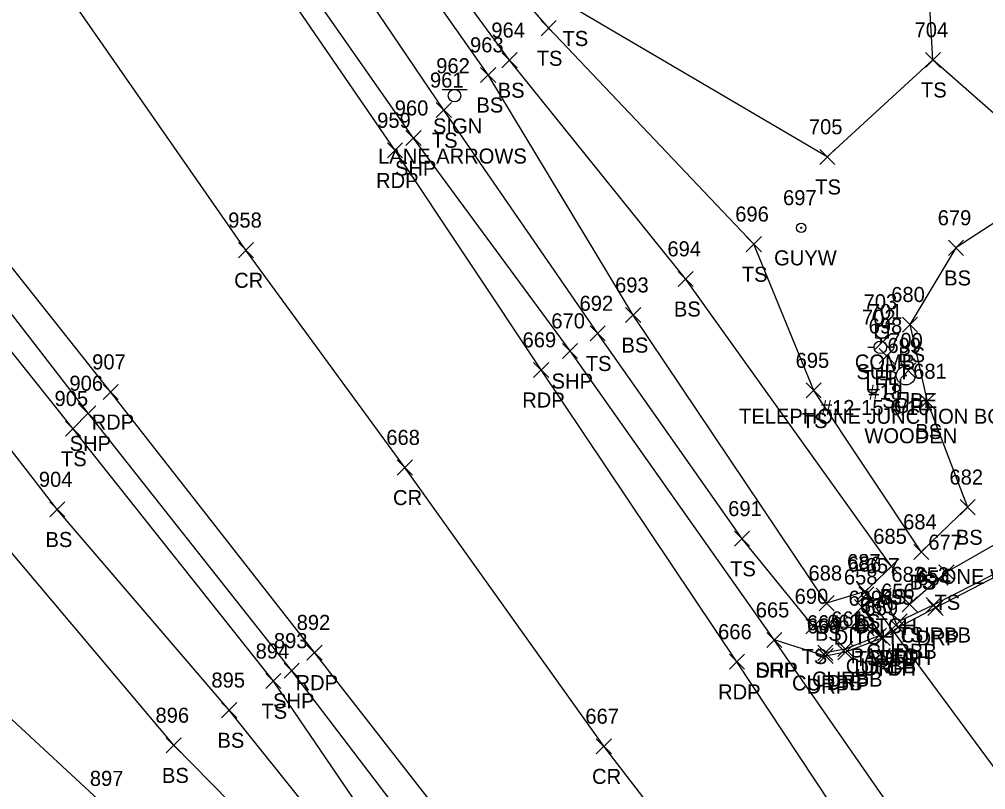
# Model space of a CAD drawing. Extents: x 1623612 to 1625808, y 621345 to 627748.
# Drawn here: x 1624906.2 to 1625034.6, y 626000.5 to 626102.9 of the extents above; entities that cross this region are included whole.
import ezdxf

# ---------------------------------------------------------------- set-up
doc = ezdxf.new("R2010")
doc.units = 0
for name, color, linetype in [('D_A', 7, 'Continuous'), ('D_C', 7, 'Continuous'), ('D_I', 7, 'Continuous'), ('D_TIC', 7, 'Continuous'), ('DCP', 7, 'Continuous'), ('DD', 7, 'Continuous'), ('L_A', 7, 'Continuous'), ('L_I', 7, 'Continuous'), ('L_TIC', 7, 'Continuous'), ('LELB', 7, 'Continuous'), ('LSOGP', 7, 'Continuous'), ('P_A', 7, 'Continuous'), ('P_I', 7, 'Continuous'), ('P_TIC', 7, 'Continuous'), ('PET', 7, 'Continuous'), ('PRC', 7, 'Continuous'), ('PSP', 7, 'Continuous'), ('R_A', 7, 'Continuous'), ('R_C', 7, 'Continuous'), ('R_I', 7, 'Continuous'), ('R_TIC', 7, 'Continuous'), ('RC', 7, 'Continuous'), ('RDP', 7, 'Continuous'), ('RGP', 7, 'Continuous'), ('S_A', 7, 'Continuous'), ('S_C', 7, 'Continuous'), ('S_I', 7, 'Continuous'), ('SSGN', 7, 'Continuous'), ('U_A', 7, 'Continuous'), ('U_C', 7, 'Continuous'), ('U_I', 7, 'Continuous'), ('U_TIC', 7, 'Continuous'), ('UDEFAULT', 7, 'Continuous'), ('UP', 7, 'Continuous'), ('UPGW', 7, 'Continuous')]:
    doc.layers.add(name, color=color, linetype=linetype)

msp = doc.modelspace()

# ---------------------------------------------------------------- linework, layer by layer
at = {"layer": 'D_TIC'}
for points in [[(1625017.74, 626025.52), (1625019.74, 626027.52)], [(1625019.74, 626025.52), (1625017.74, 626027.52)], [(1625020.06, 626025.33), (1625022.06, 626027.33)], [(1625022.06, 626025.33), (1625020.06, 626027.33)], [(1625017.17, 626023.82), (1625019.17, 626025.82)], [(1625019.17, 626023.82), (1625017.17, 626025.82)], [(1625021.95, 626021.12), (1625023.95, 626023.12)], [(1625023.95, 626021.12), (1625021.95, 626023.12)], [(1625019.92, 626019.71), (1625021.92, 626021.71)], [(1625021.92, 626019.71), (1625019.92, 626021.71)]]:
    msp.add_lwpolyline(points, dxfattribs=at)
at = {"layer": 'DCP'}
msp.add_lwpolyline([(1625053.65, 625979.21), (1625018.74, 626026.52)], dxfattribs=at)
at = {"layer": 'DD'}
msp.add_lwpolyline([(1625022.95, 626022.12), (1625021.06, 626026.33), (1625018.17, 626024.82), (1625020.92, 626020.71)], dxfattribs=at)
at = {"layer": 'L_TIC'}
for points in [[(1624975.55, 626100.74), (1624977.55, 626102.74)], [(1624977.55, 626100.74), (1624975.55, 626102.74)], [(1624970.34, 626096.49), (1624972.34, 626098.49)], [(1624972.34, 626096.49), (1624970.34, 626098.49)], [(1625026.59, 626096.53), (1625028.59, 626098.53)], [(1625028.59, 626096.53), (1625026.59, 626098.53)], [(1624967.51, 626094.53), (1624969.51, 626096.53)], [(1624969.51, 626094.53), (1624967.51, 626096.53)], [(1624961.62, 626089.85), (1624963.62, 626091.85)], [(1624963.62, 626089.85), (1624961.62, 626091.85)], [(1625012.55, 626083.64), (1625014.55, 626085.64)], [(1625014.55, 626083.64), (1625012.55, 626085.64)], [(1625002.8, 626072.04), (1625004.8, 626074.04)], [(1625004.8, 626072.04), (1625002.8, 626074.04)], [(1625029.64, 626071.55), (1625031.64, 626073.55)], [(1625031.64, 626071.55), (1625029.64, 626073.55)], [(1624993.73, 626067.42), (1624995.73, 626069.42)], [(1624995.73, 626067.42), (1624993.73, 626069.42)], [(1624986.77, 626062.62), (1624988.77, 626064.62)], [(1624988.77, 626062.62), (1624986.77, 626064.62)], [(1625023.54, 626061.35), (1625025.54, 626063.35)], [(1625025.54, 626061.35), (1625023.54, 626063.35)], [(1624982.06, 626060.18), (1624984.06, 626062.18)], [(1624984.06, 626060.18), (1624982.06, 626062.18)], [(1625010.76, 626052.6), (1625012.76, 626054.6)], [(1625012.76, 626052.6), (1625010.76, 626054.6)], [(1625025.8, 626051.15), (1625027.8, 626053.15)], [(1625027.8, 626051.15), (1625025.8, 626053.15)], [(1624912.35, 626047.53), (1624914.35, 626049.53)], [(1624914.35, 626047.53), (1624912.35, 626049.53)], [(1624910.27, 626036.79), (1624912.27, 626038.79)], [(1624912.27, 626036.79), (1624910.27, 626038.79)], [(1625031.19, 626037.09), (1625033.19, 626039.09)], [(1625033.19, 626037.09), (1625031.19, 626039.09)], [(1625001.24, 626032.9), (1625003.24, 626034.9)], [(1625003.24, 626032.9), (1625001.24, 626034.9)], [(1625025.04, 626031.14), (1625027.04, 626033.14)], [(1625027.04, 626031.14), (1625025.04, 626033.14)], [(1625025.04, 626031.14), (1625027.04, 626033.14)], [(1625027.04, 626031.14), (1625025.04, 626033.14)], [(1625021.07, 626029.22), (1625023.07, 626031.22)], [(1625023.07, 626029.22), (1625021.07, 626031.22)], [(1625021.07, 626029.22), (1625023.07, 626031.22)], [(1625023.07, 626029.22), (1625021.07, 626031.22)], [(1625028.39, 626028.44), (1625030.39, 626030.44)], [(1625030.39, 626028.44), (1625028.39, 626030.44)], [(1625017.59, 626025.86), (1625019.59, 626027.86)], [(1625019.59, 626025.86), (1625017.59, 626027.86)], [(1625012.47, 626024.33), (1625014.47, 626026.33)], [(1625014.47, 626024.33), (1625012.47, 626026.33)], [(1625023.48, 626024.16), (1625025.48, 626026.16)], [(1625025.48, 626024.16), (1625023.48, 626026.16)], [(1625010.72, 626021.24), (1625012.72, 626023.24)], [(1625012.72, 626021.24), (1625010.72, 626023.24)], [(1625017.79, 626020.99), (1625019.79, 626022.99)], [(1625019.79, 626020.99), (1625017.79, 626022.99)], [(1624938.98, 626013.97), (1624940.98, 626015.97)], [(1624940.98, 626013.97), (1624938.98, 626015.97)], [(1624933.11, 626010.11), (1624935.11, 626012.11)], [(1624935.11, 626010.11), (1624933.11, 626012.11)], [(1624925.74, 626005.44), (1624927.74, 626007.44)], [(1624927.74, 626005.44), (1624925.74, 626007.44)]]:
    msp.add_lwpolyline(points, dxfattribs=at)
at = {"layer": 'LELB'}
for points in [[(1624922.62, 625919.78), (1624947.1, 625948.56), (1624957.29, 625967.96), (1624961.07, 625979.24), (1624958.14, 625988.32), (1624939.98, 626014.97), (1624913.35, 626048.53), (1624887.64, 626080.72), (1624849.69, 626124.89), (1624827.87, 626147.28), (1624809.41, 626168.54), (1624784.36, 626180.38), (1624768.54, 626181.82), (1624752.66, 626178.59), (1624735.62, 626165.38), (1624717.35, 626142.72), (1624703.97, 626118.88), (1624686.38, 626080.62)], [(1624955.96, 625983.78), (1624934.11, 626011.11), (1624911.27, 626037.79), (1624882.4, 626075.05), (1624844.35, 626119.9), (1624824.36, 626144.8), (1624806.17, 626164.83), (1624787.45, 626176.55), (1624783.93, 626178.73), (1624767.98, 626179.73), (1624754.07, 626176), (1624742, 626162.74), (1624739.77, 626159.16), (1624724.1, 626139.19), (1624712.05, 626114.81), (1624693.63, 626076.88), (1624682.43, 626045.31), (1624675.97, 626009.13), (1624661.01, 625972.63), (1624643.83, 625915.97), (1624628.3, 625870.19), (1624627.01, 625849.3)], [(1624955.96, 625983.78), (1624951.7, 625981.09), (1624926.74, 626006.44), (1624903, 626034.62), (1624876.22, 626070.88), (1624844.75, 626108.46), (1624819.16, 626140.11), (1624799.87, 626157.38), (1624783.22, 626162.54), (1624755.55, 626163.6), (1624745.94, 626159.17), (1624742.5, 626157.44), (1624728.24, 626136.03), (1624714.3, 626113.6), (1624699.16, 626074.97), (1624693.78, 626039.85), (1624688.78, 626004.07), (1624672.44, 625966.06), (1624654.5, 625913.12), (1624647.49, 625863.39), (1624632.05, 625839.96), (1624633.8, 625804.37), (1624607.9, 625781.97), (1624576.85, 625750.09)], [(1625027.59, 626097.53), (1625013.55, 626084.64), (1624979.97, 626104.37), (1624954.09, 626138.14), (1624945.55, 626148.22)], [(1624950.51, 625967.41), (1624917.97, 625998.05), (1624890.03, 626023.9), (1624863.39, 626055.21), (1624827.77, 626091.06), (1624802.93, 626124.92), (1624791, 626136.13), (1624749.2, 626141.33), (1624736.73, 626113.9), (1624711.77, 626069.81), (1624693.78, 626039.85)], [(1625026.04, 626032.14), (1625011.76, 626053.6), (1625003.8, 626073.04), (1624976.55, 626101.74), (1624945.6, 626137.25), (1624941.49, 626135.55), (1624937.63, 626127.8)], [(1625022.07, 626030.22), (1625018.59, 626026.86), (1625013.47, 626025.33), (1624987.77, 626063.62), (1624968.51, 626095.53), (1624943.29, 626131.48), (1624945.22, 626133.16)], [(1625022.07, 626030.22), (1624994.73, 626068.42), (1624971.34, 626097.49), (1624945.22, 626133.16)], [(1625018.79, 626021.99), (1625011.72, 626022.24), (1625002.24, 626033.9), (1624983.06, 626061.18), (1624962.62, 626090.85), (1624937.63, 626127.8)], [(1625045.18, 626082.05), (1625030.64, 626072.55), (1625024.54, 626062.35), (1625026.8, 626052.15), (1625032.19, 626038.09), (1625026.04, 626032.14)], [(1625058.49, 626067.08), (1625039.14, 626056.58), (1625038.67, 626047.76), (1625042.58, 626036.99), (1625029.39, 626029.44), (1625024.48, 626025.16)]]:
    msp.add_lwpolyline(points, dxfattribs=at)
at = {"layer": 'LSOGP'}
msp.add_lwpolyline([(1625200.23, 625842.69), (1625180.7, 625879.29), (1625153.81, 625905.72), (1625139.96, 625942.2), (1625106.19, 625988.13), (1625099.02, 625990.77), (1625092.97, 625994.26), (1625089.75, 626000.84), (1625088.99, 626008.69), (1625090.67, 626015.53), (1625069.92, 626043.19), (1625069.59, 626043.56), (1625065.69, 626051.8), (1625058.49, 626067.08), (1625045.18, 626082.05), (1625027.59, 626097.53), (1625025.64, 626131.89)], dxfattribs=at)
at = {"layer": 'P_TIC'}
for points in [[(1624957.59, 626086.14), (1624959.59, 626088.14)], [(1624959.59, 626086.14), (1624957.59, 626088.14)], [(1624955.14, 626084.5), (1624957.14, 626086.5)], [(1624957.14, 626084.5), (1624955.14, 626086.5)], [(1624935.34, 626071.24), (1624937.34, 626073.24)], [(1624937.34, 626071.24), (1624935.34, 626073.24)], [(1624978.39, 626057.85), (1624980.39, 626059.85)], [(1624980.39, 626057.85), (1624978.39, 626059.85)], [(1624974.55, 626055.33), (1624976.55, 626057.33)], [(1624976.55, 626055.33), (1624974.55, 626057.33)], [(1624917.36, 626052.4), (1624919.36, 626054.4)], [(1624919.36, 626052.4), (1624917.36, 626054.4)], [(1624914.38, 626049.56), (1624916.38, 626051.56)], [(1624916.38, 626049.56), (1624914.38, 626051.56)], [(1624956.44, 626042.36), (1624958.44, 626044.36)], [(1624958.44, 626042.36), (1624956.44, 626044.36)], [(1625005.51, 626019.44), (1625007.51, 626021.44)], [(1625007.51, 626019.44), (1625005.51, 626021.44)], [(1624944.44, 626017.77), (1624946.44, 626019.77)], [(1624946.44, 626017.77), (1624944.44, 626019.77)], [(1625000.56, 626016.54), (1625002.56, 626018.54)], [(1625002.56, 626016.54), (1625000.56, 626018.54)], [(1624941.41, 626015.35), (1624943.41, 626017.35)], [(1624943.41, 626015.35), (1624941.41, 626017.35)], [(1624982.87, 626005.31), (1624984.87, 626007.31)], [(1624984.87, 626005.31), (1624982.87, 626007.31)]]:
    msp.add_lwpolyline(points, dxfattribs=at)
at = {"layer": 'PET'}
for points in [[(1625223.77, 625705.98), (1625197.34, 625741.92), (1625177.42, 625768.95), (1625149.4, 625806.39), (1625126.15, 625837.91), (1625100.61, 625872.87), (1625078.39, 625904.23), (1625050.83, 625943.53), (1625026.61, 625979.68), (1625001.56, 626017.54), (1624975.55, 626056.33), (1624956.14, 626085.5), (1624926, 626129.47), (1624907.51, 626155.92), (1624881.56, 626192.36), (1624859.36, 626223.09), (1624835.81, 626254.93), (1624815.05, 626283.37), (1624795.69, 626312.41), (1624789.97, 626324.03), (1624786.26, 626337.17), (1624785.07, 626353.04), (1624787.66, 626371.25), (1624792.4, 626386.87)], [(1625203.84, 625692.06), (1625178.56, 625725.93), (1625159.1, 625752.13), (1625138.75, 625779.51), (1625115.85, 625810.21), (1625086.53, 625849.64), (1625062.28, 625882.29), (1625040.04, 625911.41), (1625011.87, 625940.67), (1624992.38, 625961.15), (1624963.94, 625995.04), (1624945.44, 626018.77), (1624918.36, 626053.4), (1624893.3, 626084.98), (1624858.44, 626129.32)]]:
    msp.add_lwpolyline(points, dxfattribs=at)
at = {"layer": 'PRC'}
msp.add_lwpolyline([(1625213.58, 625698.73), (1625187.25, 625734.61), (1625167.02, 625761.6), (1625139.37, 625799.19), (1625115.73, 625830.47), (1625089.34, 625866.2), (1625066.75, 625896.39), (1625037.44, 625935.12), (1625012.58, 625969.02), (1624983.87, 626006.31), (1624957.44, 626043.36), (1624936.34, 626072.24), (1624905.82, 626116.16), (1624884.45, 626141.57), (1624859.03, 626175.57)], dxfattribs=at)
at = {"layer": 'PSP'}
for points in [[(1625197.89, 625687.83), (1625193.57, 625693.81), (1625173.65, 625722.07), (1625153.52, 625749.21), (1625132.81, 625774.23), (1625108.64, 625805.39), (1625079.11, 625843.61), (1625053.93, 625876.29), (1625030.83, 625905.94), (1625006.8, 625934.64), (1624989.43, 625958.35), (1624960.91, 625992.11), (1624942.41, 626016.35), (1624915.38, 626050.56), (1624890.43, 626082.85), (1624855.5, 626126.62)], [(1625229.23, 625710.23), (1625203.41, 625745.51), (1625190.36, 625762.87), (1625182.48, 625773.25), (1625155.83, 625810.32), (1625133.5, 625842.77), (1625108.2, 625877.47), (1625085.19, 625909.84), (1625057.82, 625948.13), (1625042.32, 625969.75), (1625027.64, 625990.04), (1625006.51, 626020.44), (1624979.39, 626058.85), (1624958.59, 626087.14), (1624930.55, 626127.2)]]:
    msp.add_lwpolyline(points, dxfattribs=at)
at = {"layer": 'R_TIC'}
for points in [[(1625026.69, 626024.1), (1625028.69, 626026.1)], [(1625028.69, 626024.1), (1625026.69, 626026.1)], [(1625026.93, 626023.71), (1625028.93, 626025.71)], [(1625028.93, 626023.71), (1625026.93, 626025.71)], [(1625022.16, 626021.93), (1625024.16, 626023.93)], [(1625024.16, 626021.93), (1625022.16, 626023.93)], [(1625021.95, 626021.12), (1625023.95, 626023.12)], [(1625023.95, 626021.12), (1625021.95, 626023.12)], [(1625005.51, 626019.44), (1625007.51, 626021.44)], [(1625007.51, 626019.44), (1625005.51, 626021.44)], [(1625019.42, 626020), (1625021.42, 626022)], [(1625021.42, 626020), (1625019.42, 626022)], [(1625019.92, 626019.71), (1625021.92, 626021.71)], [(1625021.92, 626019.71), (1625019.92, 626021.71)], [(1625014.95, 626018.24), (1625016.95, 626020.24)], [(1625016.95, 626018.24), (1625014.95, 626020.24)], [(1625012.29, 626017.73), (1625014.29, 626019.73)], [(1625014.29, 626017.73), (1625012.29, 626019.73)], [(1625012.33, 626017.3), (1625014.33, 626019.3)], [(1625014.33, 626017.3), (1625012.33, 626019.3)], [(1625014.97, 626017.8), (1625016.97, 626019.8)], [(1625016.97, 626017.8), (1625014.97, 626019.8)]]:
    msp.add_lwpolyline(points, dxfattribs=at)
at = {"layer": 'RC'}
for points in [[(1625069.59, 626043.56), (1625057.37, 626039.13), (1625043.4, 626033.1), (1625027.69, 626025.1), (1625023.16, 626022.93)], [(1625020.42, 626021), (1625015.95, 626019.24), (1625013.29, 626018.73)]]:
    msp.add_lwpolyline(points, dxfattribs=at)
at = {"layer": 'RDP'}
msp.add_lwpolyline([(1625069.92, 626043.19), (1625057.28, 626038.97), (1625043.66, 626032.88), (1625027.93, 626024.71), (1625022.95, 626022.12), (1625020.92, 626020.71), (1625015.97, 626018.8), (1625013.33, 626018.3), (1625006.51, 626020.44)], dxfattribs=at)
at = {"layer": 'RGP'}
msp.add_line((1625023.97, 626055.58), (1625023.97, 626055.58), dxfattribs=at)
for radius in [1.25, 0.0833]:
    msp.add_circle((1625023.97, 626055.58), radius, dxfattribs=at)
at = {"layer": 'SSGN'}
for p, q in [((1624962.39, 626093.6), (1624965.73, 626093.6)), ((1624964.04, 626092.77), (1624964.04, 626092.77))]:
    msp.add_line(p, q, dxfattribs=at)
msp.add_circle((1624964.04, 626092.77), 0.833, dxfattribs=at)
at = {"layer": 'U_TIC'}
for points in [[(1625019.93, 626059.09), (1625021.93, 626061.09)], [(1625021.93, 626059.09), (1625019.93, 626061.09)], [(1625023.31, 626055.25), (1625025.31, 626057.25)], [(1625025.31, 626055.25), (1625023.31, 626057.25)]]:
    msp.add_lwpolyline(points, dxfattribs=at)
at = {"layer": 'UDEFAULT'}
for points in [[(1625020.46, 626057.17), (1625022.46, 626059.17)], [(1625022.46, 626057.17), (1625020.46, 626059.17)]]:
    msp.add_lwpolyline(points, dxfattribs=at)
at = {"layer": 'UP'}
for p, q in [((1625021.07, 626063.05), (1625020.82, 626062.21)), ((1625019.99, 626060.55), (1625019.99, 626062.21)), ((1625019.99, 626062.21), (1625021.65, 626062.21)), ((1625020.82, 626061.38), (1625020.82, 626061.38)), ((1625021.65, 626062.21), (1625021.65, 626060.55)), ((1625021.65, 626060.55), (1625019.99, 626060.55)), ((1625020.57, 626059.71), (1625020.82, 626060.55)), ((1625018.94, 626059.33), (1625019.76, 626059.33)), ((1625020.6, 626059.33), (1625020.6, 626059.33)), ((1625022.26, 626059.33), (1625021.43, 626059.33)), ((1625021.43, 626059.33), (1625021.43, 626059.33)), ((1625022.26, 626059.33), (1625022.26, 626059.33))]:
    msp.add_line(p, q, dxfattribs=at)
for centre in [(1625020.82, 626061.38), (1625020.6, 626059.33)]:
    msp.add_circle(centre, 0.833, dxfattribs=at)
at = {"layer": 'UPGW'}
for radius in [0.625, 0.0833]:
    msp.add_circle((1625010.09, 626075.22), radius, dxfattribs=at)

# ---------------------------------------------------------------- texts
at = {"layer": 'D_A'}
for s, p in [('DITCH', (1625017.29, 626021.33)), ('P', (1625018.12, 626021.52)), ('DITCH', (1625014.4, 626019.82)), ('DITCH', (1625019.19, 626017.12)), ('DITCH', (1625017.16, 626015.71))]:
    msp.add_text(s, height=2, dxfattribs=at).set_placement(p)
at = {"layer": 'D_C'}
msp.add_text('PAVED', height=2, dxfattribs=at).set_placement((1625016.64, 626017.33))
at = {"layer": 'D_I'}
for s, p in [('686', (1625016.28, 626029.52)), ('657', (1625018.65, 626029.33)), ('658', (1625015.76, 626027.82)), ('655', (1625020.54, 626025.12)), ('659', (1625018.5, 626023.71))]:
    msp.add_text(s, height=2, dxfattribs=at).set_placement(p)
at = {"layer": 'L_A'}
for s, p in [('TS', (1624978.38, 626099.37)), ('TS', (1624974.96, 626096.74)), ('BS', (1624969.78, 626092.49)), ('TS', (1625026, 626092.53)), ('BS', (1624966.95, 626090.53)), ('TS', (1624961.03, 626085.85)), ('TS', (1625011.96, 626079.64)), ('TS', (1625002.2, 626068.04)), ('BS', (1625029.08, 626067.55)), ('BS', (1624993.18, 626063.42)), ('BS', (1624986.22, 626058.62)), ('BS', (1625022.98, 626057.35)), ('TS', (1624981.47, 626056.18)), ('TS', (1625010.17, 626048.6)), ('BS', (1625025.24, 626047.15)), ('TS', (1624911.76, 626043.53)), ('BS', (1624909.71, 626032.79)), ('BS', (1625030.63, 626033.09)), ('TS', (1625000.65, 626028.9)), ('TS', (1625024.45, 626027.14)), ('BS', (1625024.48, 626027.14)), ('BS', (1625020.51, 626025.22)), ('BS', (1625020.51, 626025.22)), ('TS', (1625027.8, 626024.44)), ('BS', (1625017.03, 626021.86)), ('BS', (1625011.91, 626020.33)), ('TS', (1625022.89, 626020.16)), ('TS', (1625010.13, 626017.24)), ('TS', (1625017.2, 626016.99)), ('TS', (1624938.39, 626009.97)), ('BS', (1624932.55, 626006.11)), ('BS', (1624925.18, 626001.44))]:
    msp.add_text(s, height=2, dxfattribs=at).set_placement(p)
at = {"layer": 'L_I'}
for s, p in [('964', (1624968.93, 626100.49)), ('704', (1625025.15, 626100.53)), ('963', (1624966.1, 626098.53)), ('961', (1624960.78, 626093.85)), ('705', (1625011.11, 626087.64)), ('696', (1625001.33, 626076.04)), ('679', (1625028.22, 626075.55)), ('694', (1624992.32, 626071.42)), ('693', (1624985.37, 626066.62)), ('692', (1624980.65, 626064.18)), ('680', (1625022.05, 626065.35)), ('695', (1625009.35, 626056.6)), ('681', (1625024.96, 626055.15)), ('905', (1624910.91, 626051.53)), ('682', (1625029.78, 626041.09)), ('904', (1624908.83, 626040.79)), ('691', (1625000.39, 626036.9)), ('684', (1625023.63, 626035.14)), ('684', (1625023.63, 626035.14)), ('685', (1625019.66, 626033.22)), ('685', (1625019.66, 626033.22)), ('677', (1625026.98, 626032.44)), ('687', (1625016.18, 626029.86)), ('688', (1625011.06, 626028.33)), ('683', (1625022.07, 626028.16)), ('690', (1625009.22, 626025.24)), ('689', (1625016.37, 626024.99)), ('894', (1624937.62, 626017.97)), ('895', (1624931.75, 626014.11)), ('896', (1624924.32, 626009.44)), ('897', (1624915.6, 626001.05))]:
    msp.add_text(s, height=2, dxfattribs=at).set_placement(p)
at = {"layer": 'P_A'}
for s, p in [('SHP', (1624956.13, 626082.14)), ('RDP', (1624953.62, 626080.5)), ('CR', (1624934.77, 626067.24)), ('SHP', (1624976.93, 626053.85)), ('RDP', (1624973.03, 626051.33)), ('RDP', (1624915.84, 626048.4)), ('SHP', (1624912.92, 626045.56)), ('CR', (1624955.87, 626038.36)), ('SHP', (1625004.04, 626015.44)), ('RDP', (1624942.92, 626013.77)), ('RDP', (1624999.05, 626012.54)), ('SHP', (1624939.94, 626011.35)), ('CR', (1624982.31, 626001.31))]:
    msp.add_text(s, height=2, dxfattribs=at).set_placement(p)
at = {"layer": 'P_I'}
for s, p in [('960', (1624956.1, 626090.14)), ('959', (1624953.77, 626088.5)), ('958', (1624933.98, 626075.24)), ('670', (1624976.9, 626061.85)), ('669', (1624973.08, 626059.33)), ('907', (1624915.91, 626056.4)), ('906', (1624912.89, 626053.56)), ('668', (1624954.98, 626046.36)), ('665', (1625004.05, 626023.44)), ('892', (1624943.07, 626021.77)), ('666', (1624999.05, 626020.54)), ('893', (1624940.05, 626019.35)), ('667', (1624981.42, 626009.31))]:
    msp.add_text(s, height=2, dxfattribs=at).set_placement(p)
at = {"layer": 'R_A'}
for s, p in [('GP', (1625022.4, 626050.58)), ('CURBB', (1625023.28, 626020.1)), ('DRP', (1625025.42, 626019.71)), ('CURBB', (1625018.74, 626017.93)), ('DRP', (1625020.44, 626017.12)), ('DRP', (1625004, 626015.44)), ('CURBB', (1625016.01, 626016)), ('DRP', (1625018.41, 626015.71)), ('CURBB', (1625011.53, 626014.24)), ('CURBB', (1625008.87, 626013.73)), ('DRP', (1625010.82, 626013.3)), ('DRP', (1625013.46, 626013.8))]:
    msp.add_text(s, height=2, dxfattribs=at).set_placement(p)
at = {"layer": 'R_C'}
msp.add_text('WOODEN', height=2, dxfattribs=at).set_placement((1625018.48, 626046.58))
at = {"layer": 'R_I'}
for s, p in [('699', (1625021.55, 626058.58)), ('653', (1625025.28, 626028.1)), ('654', (1625025.52, 626027.71)), ('656', (1625020.7, 626025.93)), ('655', (1625020.54, 626025.12)), ('665', (1625004.05, 626023.44)), ('660', (1625017.88, 626024)), ('659', (1625018.5, 626023.71)), ('662', (1625013.52, 626021.8)), ('661', (1625014.06, 626022.24)), ('664', (1625010.83, 626021.73)), ('663', (1625010.87, 626021.3))]:
    msp.add_text(s, height=2, dxfattribs=at).set_placement(p)
at = {"layer": 'S_A'}
msp.add_text('SIGN', height=2, dxfattribs=at).set_placement((1624961.18, 626087.75))
at = {"layer": 'S_C'}
for s, p in [('LANE ARROWS', (1624953.88, 626083.75)), ('ONE WAY/ DO NOT ENTER', (1625028.63, 626027.89))]:
    msp.add_text(s, height=2, dxfattribs=at).set_placement(p)
at = {"layer": 'S_I'}
msp.add_text('962', height=2, dxfattribs=at).set_placement((1624961.61, 626095.75))
at = {"layer": 'U_A'}
for s, p in [('GUYW', (1625006.49, 626070.22)), ('COMB', (1625017.21, 626056.38)), ('SUBT', (1625017.43, 626055.09)), ('TEL', (1625018.16, 626054.33)), ('UTIL', (1625018.62, 626053.17)), ('SUBE', (1625020.85, 626051.25))]:
    msp.add_text(s, height=2, dxfattribs=at).set_placement(p)
at = {"layer": 'U_C'}
for s, p in [('#18', (1625019.02, 626052.38)), ('#12-15-6/10', (1625012.7, 626050.33)), ('TELEPHONE JUNCTION BOX', (1625001.83, 626049.17))]:
    msp.add_text(s, height=2, dxfattribs=at).set_placement(p)
at = {"layer": 'U_I'}
for s, p in [('697', (1625007.68, 626078.22)), ('703', (1625018.38, 626064.38)), ('701', (1625019.06, 626063.09)), ('702', (1625018.16, 626062.33)), ('698', (1625019.05, 626061.17)), ('700', (1625021.78, 626059.25))]:
    msp.add_text(s, height=2, dxfattribs=at).set_placement(p)

doc.saveas('drawing.dxf')
